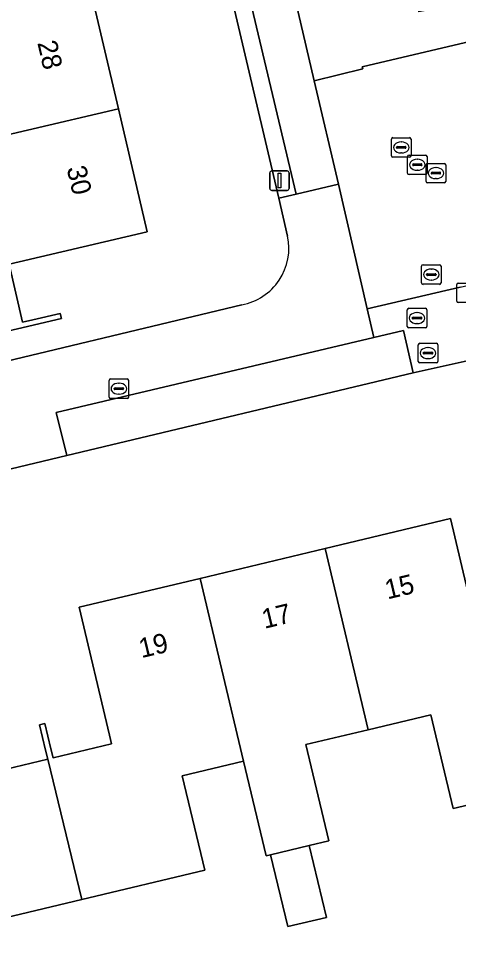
# Model space of a CAD drawing. Extents: x 157648 to 158502, y 379212 to 380938.
# Drawn here: x 158099.34 to 158121.86, y 380779.75 to 380827.8 of the extents above; entities that cross this region are included whole.
import ezdxf

# ---------------------------------------------------------------- set-up
doc = ezdxf.new("R2010")
doc.units = 0
for name, color, linetype in [('IMGEO_Brandkraan', 7, 'Continuous'), ('IMGEO_Erf', 7, 'Continuous'), ('IMGEO_Kolk', 7, 'Continuous'), ('IMGEO_Lichtmast', 7, 'Continuous'), ('IMGEO_Pand', 7, 'Continuous'), ('IMGEO_Pand_nummerreeks', 7, 'Continuous'), ('IMGEO_Parkeervlak_open', 7, 'Continuous'), ('IMGEO_Rijbaan_lokaal_open', 7, 'Continuous'), ('IMGEO_Rioolput', 7, 'Continuous'), ('IMGEO_Voetpad_open', 7, 'Continuous')]:
    doc.layers.add(name, color=color, linetype=linetype)

msp = doc.modelspace()

# ---------------------------------------------------------------- linework, layer by layer
at = {"layer": 'IMGEO_Brandkraan'}
for p, q in [((158119.808, 380810.256), (158119.808, 380811.108)), ((158119.883, 380811.182), (158120.735, 380811.182)), ((158120.296, 380810.962), (158120.321, 380810.962)), ((158120.809, 380811.108), (158120.809, 380810.256)), ((158120.067, 380810.676), (158120.067, 380810.688)), ((158120.505, 380810.639), (158120.107, 380810.639)), ((158120.11, 380810.725), (158120.508, 380810.725)), ((158120.319, 380810.402), (158120.294, 380810.402)), ((158120.551, 380810.688), (158120.551, 380810.676)), ((158120.735, 380810.182), (158119.883, 380810.182))]:
    msp.add_line(p, q, dxfattribs=at)
for points in [[(158119.808, 380810.256), (158119.808, 380811.108)], [(158119.883, 380811.182), (158120.735, 380811.182)], [(158120.809, 380811.108), (158120.809, 380810.256)], [(158120.735, 380810.182), (158119.883, 380810.182)]]:
    msp.add_lwpolyline(points, dxfattribs=at)
for centre, radius, start, end in [((158119.885, 380811.106), 0.0765, 91.552, 178.448), ((158119.885, 380811.106), 0.0765, 91.552, 178.448), ((158120.733, 380811.106), 0.0765, 1.552, 88.448), ((158120.733, 380811.106), 0.0765, 1.552, 88.448), ((158120.107, 380810.685), 0.0403, 85.8775, 175.7526), ((158120.104, 380810.675), 0.0366, 178.938, 274.7102), ((158120.508, 380810.682), 0.043, 264.8664, 352.4533), ((158120.512, 380810.687), 0.0386, 1.7309, 96.639), ((158119.885, 380810.258), 0.0765, 181.552, 268.448), ((158119.885, 380810.258), 0.0765, 181.552, 268.448), ((158120.733, 380810.258), 0.0765, 271.552, 358.448), ((158120.733, 380810.258), 0.0765, 271.552, 358.448)]:
    msp.add_arc(centre, radius, start, end, dxfattribs=at)
for centre, major_axis, ratio, start_param, end_param in [((158120.295, 380810.682), (-0.387, 0.002), 0.722429, 4.712389, 7.853982), ((158120.32, 380810.682), (-0.39, 0.002), 0.717154, 1.570796, 4.712389)]:
    msp.add_ellipse(centre, major_axis=major_axis, ratio=ratio, start_param=start_param, end_param=end_param, dxfattribs=at)
at = {"layer": 'IMGEO_Erf'}
for points in [[(158112.661, 380818.608), (158109.015, 380834.139), (158111.901, 380834.843), (158108.155, 380850.952), (158098.578, 380848.911), (158098.721, 380848.273), (158081.927, 380844.31), (158083.842, 380835.218), (158083.573, 380834.808), (158085.236, 380827.701), (158085.65, 380825.523), (158085.654, 380825.501), (158080.898, 380824.355), (158081.233, 380821.82), (158083.782, 380822.407), (158084.461, 380819.455), (158081.913, 380818.868), (158082.159, 380817.801), (158083.472, 380818.135), (158085.867, 380807.201), (158095.372, 380809.473), (158110.763, 380813.16)], [(158102.923, 380829.722), (158104.45, 380823.191), (158105.923, 380816.888), (158099.37, 380815.357), (158098.844, 380815.234), (158099.539, 380812.265), (158100.065, 380812.388), (158101.466, 380812.716), (158101.528, 380812.45), (158092.502, 380810.34), (158091.032, 380816.63), (158095.864, 380817.759), (158095.105, 380821.005), (158094.347, 380824.251), (158089.612, 380823.144), (158088.882, 380826.268), (158088.37, 380828.461)], [(158113.115, 380816.675), (158112.661, 380818.608)], [(158122.924, 380810.424), (158119.554, 380809.668), (158101.803, 380805.439), (158080.044, 380800.241), (158087.197, 380759.348)], [(158086.779, 380778.918), (158083.38, 380793.171), (158089.674, 380794.672), (158096.153, 380796.217), (158097.717, 380789.661), (158097.832, 380789.177), (158100.83, 380789.892), (158100.72, 380790.357), (158100.413, 380791.653), (158100.684, 380791.718), (158100.992, 380790.419), (158101.102, 380789.956), (158104.099, 380790.671), (158103.993, 380791.115), (158102.43, 380797.671), (158108.628, 380799.149), (158115.035, 380800.677), (158121.466, 380802.212), (158123.132, 380795.125)], [(158126.111, 380788.429), (158121.596, 380787.367), (158120.451, 380792.165), (158117.248, 380791.401), (158114.043, 380790.637), (158115.219, 380785.708), (158114.224, 380785.471), (158115.101, 380781.794), (158113.123, 380781.322), (158112.246, 380784.999), (158112.016, 380784.944), (158110.859, 380789.796), (158107.719, 380789.047), (158108.871, 380784.219), (158102.572, 380782.717), (158096.276, 380781.216), (158095.657, 380783.815), (158092.447, 380783.05), (158091.912, 380785.292), (158088.703, 380784.527), (158089.865, 380779.654)]]:
    msp.add_lwpolyline(points, dxfattribs=at)
msp.add_arc((158110.248, 380816.049), 2.934, 280.1029, 12.3216, dxfattribs=at)
at = {"layer": 'IMGEO_Kolk'}
for p, q in [((158119.259, 380819.896), (158119.259, 380820.748)), ((158119.334, 380820.822), (158120.186, 380820.822)), ((158119.561, 380820.365), (158119.959, 380820.365)), ((158119.747, 380820.602), (158119.772, 380820.602)), ((158120.26, 380820.748), (158120.26, 380819.896)), ((158119.518, 380820.316), (158119.518, 380820.328)), ((158119.956, 380820.279), (158119.558, 380820.279)), ((158119.77, 380820.042), (158119.745, 380820.042)), ((158120.002, 380820.328), (158120.002, 380820.316)), ((158120.186, 380819.822), (158119.334, 380819.822)), ((158119.244, 380812.048), (158119.244, 380812.9)), ((158119.319, 380812.974), (158120.171, 380812.974)), ((158119.732, 380812.754), (158119.757, 380812.754)), ((158120.245, 380812.9), (158120.245, 380812.048)), ((158119.503, 380812.468), (158119.503, 380812.48)), ((158119.941, 380812.431), (158119.543, 380812.431)), ((158119.546, 380812.517), (158119.944, 380812.517)), ((158119.755, 380812.194), (158119.73, 380812.194)), ((158119.987, 380812.48), (158119.987, 380812.468)), ((158120.171, 380811.974), (158119.319, 380811.974)), ((158104.047, 380809.359), (158104.899, 380809.359)), ((158103.972, 380808.433), (158103.972, 380809.285)), ((158104.231, 380808.853), (158104.231, 380808.865)), ((158104.274, 380808.902), (158104.672, 380808.902)), ((158104.46, 380809.139), (158104.485, 380809.139)), ((158104.715, 380808.865), (158104.715, 380808.853)), ((158104.973, 380809.285), (158104.973, 380808.433)), ((158104.899, 380808.359), (158104.047, 380808.359)), ((158104.669, 380808.816), (158104.271, 380808.816)), ((158104.483, 380808.579), (158104.458, 380808.579))]:
    msp.add_line(p, q, dxfattribs=at)
for points in [[(158119.259, 380819.896), (158119.259, 380820.748)], [(158119.334, 380820.822), (158120.186, 380820.822)], [(158120.26, 380820.748), (158120.26, 380819.896)], [(158120.186, 380819.822), (158119.334, 380819.822)], [(158119.244, 380812.048), (158119.244, 380812.9)], [(158119.319, 380812.974), (158120.171, 380812.974)], [(158120.245, 380812.9), (158120.245, 380812.048)], [(158120.171, 380811.974), (158119.319, 380811.974)], [(158104.047, 380809.359), (158104.899, 380809.359)], [(158103.972, 380808.433), (158103.972, 380809.285)], [(158104.973, 380809.285), (158104.973, 380808.433)], [(158104.899, 380808.359), (158104.047, 380808.359)]]:
    msp.add_lwpolyline(points, dxfattribs=at)
for centre, radius, start, end in [((158119.336, 380820.746), 0.0765, 91.552, 178.448), ((158119.336, 380820.746), 0.0765, 91.552, 178.448), ((158119.558, 380820.325), 0.0403, 85.8775, 175.7526), ((158119.963, 380820.327), 0.0386, 1.7309, 96.639), ((158120.184, 380820.746), 0.0765, 1.552, 88.448), ((158120.184, 380820.746), 0.0765, 1.552, 88.448), ((158119.336, 380819.898), 0.0765, 181.552, 268.448), ((158119.336, 380819.898), 0.0765, 181.552, 268.448), ((158119.555, 380820.315), 0.0366, 178.938, 274.7102), ((158119.959, 380820.322), 0.043, 264.8664, 352.4533), ((158120.184, 380819.898), 0.0765, 271.552, 358.448), ((158120.184, 380819.898), 0.0765, 271.552, 358.448), ((158119.321, 380812.898), 0.0765, 91.552, 178.448), ((158119.321, 380812.898), 0.0765, 91.552, 178.448), ((158120.169, 380812.898), 0.0765, 1.552, 88.448), ((158120.169, 380812.898), 0.0765, 1.552, 88.448), ((158119.543, 380812.477), 0.0403, 85.8775, 175.7526), ((158119.54, 380812.467), 0.0366, 178.938, 274.7102), ((158119.944, 380812.474), 0.043, 264.8664, 352.4533), ((158119.948, 380812.479), 0.0386, 1.7309, 96.639), ((158119.321, 380812.05), 0.0765, 181.552, 268.448), ((158119.321, 380812.05), 0.0765, 181.552, 268.448), ((158120.169, 380812.05), 0.0765, 271.552, 358.448), ((158120.169, 380812.05), 0.0765, 271.552, 358.448), ((158104.049, 380809.283), 0.0765, 91.552, 178.448), ((158104.049, 380809.283), 0.0765, 91.552, 178.448), ((158104.897, 380809.283), 0.0765, 1.552, 88.448), ((158104.897, 380809.283), 0.0765, 1.552, 88.448), ((158104.271, 380808.862), 0.0403, 85.8775, 175.7526), ((158104.268, 380808.852), 0.0366, 178.938, 274.7102), ((158104.672, 380808.859), 0.043, 264.8664, 352.4533), ((158104.676, 380808.864), 0.0386, 1.7309, 96.639), ((158104.049, 380808.435), 0.0765, 181.552, 268.448), ((158104.049, 380808.435), 0.0765, 181.552, 268.448), ((158104.897, 380808.435), 0.0765, 271.552, 358.448), ((158104.897, 380808.435), 0.0765, 271.552, 358.448)]:
    msp.add_arc(centre, radius, start, end, dxfattribs=at)
for centre, major_axis, ratio, start_param, end_param in [((158119.746, 380820.322), (-0.387, 0.002), 0.722429, 4.712389, 7.853982), ((158119.771, 380820.322), (-0.39, 0.002), 0.717154, 1.570796, 4.712389), ((158119.731, 380812.474), (-0.387, 0.002), 0.722429, 4.712389, 7.853982), ((158119.756, 380812.474), (-0.39, 0.002), 0.717154, 1.570796, 4.712389), ((158104.459, 380808.859), (-0.387, 0.002), 0.722429, 4.712389, 7.853982), ((158104.484, 380808.859), (-0.39, 0.002), 0.717154, 1.570796, 4.712389)]:
    msp.add_ellipse(centre, major_axis=major_axis, ratio=ratio, start_param=start_param, end_param=end_param, dxfattribs=at)
at = {"layer": 'IMGEO_Lichtmast'}
for p, q in [((158112.204, 380819.111), (158112.204, 380819.911)), ((158112.204, 380819.911), (158112.204, 380819.111)), ((158112.304, 380820.011), (158113.094, 380820.011)), ((158113.094, 380820.011), (158112.304, 380820.011)), ((158113.194, 380819.911), (158113.194, 380819.111)), ((158113.194, 380819.111), (158113.194, 380819.911)), ((158113.094, 380819.011), (158112.304, 380819.011)), ((158112.304, 380819.011), (158113.094, 380819.011))]:
    msp.add_line(p, q, dxfattribs=at)
msp.add_lwpolyline([(158112.624, 380819.886), (158112.774, 380819.886), (158112.774, 380819.136), (158112.624, 380819.136), (158112.624, 380819.886)], dxfattribs=at)
for centre, start, end in [((158112.304, 380819.911), 90, 180), ((158112.304, 380819.911), 90, 180), ((158113.094, 380819.911), 0, 90), ((158113.094, 380819.911), 360, 90), ((158112.304, 380819.111), 180, 270), ((158112.304, 380819.111), 180, 270), ((158113.094, 380819.111), 270, 0), ((158113.094, 380819.111), 270, 0)]:
    msp.add_arc(centre, 0.1, start, end, dxfattribs=at)
at = {"layer": 'IMGEO_Pand'}
for points in [[(158100.707, 380829.204), (158093.575, 380827.456), (158088.882, 380826.268), (158089.612, 380823.144), (158094.347, 380824.251), (158095.105, 380821.005), (158104.45, 380823.191), (158102.923, 380829.722), (158101.196, 380829.318)], [(158095.105, 380821.005), (158095.864, 380817.759), (158091.032, 380816.63), (158092.502, 380810.34), (158101.528, 380812.45), (158101.466, 380812.716), (158100.065, 380812.388), (158099.539, 380812.265), (158098.844, 380815.234), (158099.37, 380815.357), (158105.923, 380816.888), (158104.45, 380823.191)], [(158115.035, 380800.677), (158117.248, 380791.401), (158120.451, 380792.165), (158121.596, 380787.367), (158126.111, 380788.429), (158128.019, 380788.878), (158125.933, 380797.747), (158125.658, 380797.682), (158126.093, 380795.831), (158123.132, 380795.125), (158121.466, 380802.212)], [(158115.035, 380800.677), (158108.628, 380799.149), (158110.859, 380789.796), (158112.016, 380784.944), (158112.246, 380784.999), (158114.224, 380785.471), (158115.219, 380785.708), (158114.043, 380790.637), (158117.248, 380791.401)], [(158100.83, 380789.892), (158102.572, 380782.717), (158108.871, 380784.219), (158107.719, 380789.047), (158110.859, 380789.796), (158108.628, 380799.149), (158102.43, 380797.671), (158103.993, 380791.115), (158104.099, 380790.671), (158101.102, 380789.956), (158100.992, 380790.419), (158100.684, 380791.718), (158100.413, 380791.653), (158100.72, 380790.357)], [(158100.83, 380789.892), (158097.832, 380789.177), (158097.717, 380789.661), (158096.153, 380796.217), (158089.674, 380794.672), (158091.912, 380785.292), (158092.447, 380783.05), (158095.657, 380783.815), (158096.276, 380781.216), (158102.572, 380782.717)], [(158114.224, 380785.471), (158112.246, 380784.999), (158113.123, 380781.322), (158115.101, 380781.794)]]:
    msp.add_lwpolyline(points, close=True, dxfattribs=at)
at = {"layer": 'IMGEO_Parkeervlak_open'}
for points in [[(158114.479, 380824.622), (158113.239, 380829.916), (158111.04, 380829.398), (158113.552, 380818.819), (158115.724, 380819.327)], [(158119.554, 380809.668), (158119.044, 380811.842), (158117.53, 380811.484), (158101.267, 380807.637), (158101.803, 380805.439)]]:
    msp.add_lwpolyline(points, close=True, dxfattribs=at)
at = {"layer": 'IMGEO_Rijbaan_lokaal_open'}
msp.add_lwpolyline([(158127.817, 380827.893), (158116.939, 380825.329), (158116.965, 380825.228), (158114.479, 380824.622), (158115.724, 380819.327), (158117.193, 380812.948), (158121.954, 380814.064), (158124.652, 380814.696), (158124.54, 380815.172), (158126.195, 380819.238), (158128.598, 380819.803), (158132.721, 380820.756), (158133.896, 380821.025), (158133.871, 380821.126), (158134.261, 380821.217), (158153.272, 380825.665)], dxfattribs=at)
at = {"layer": 'IMGEO_Rioolput'}
for p, q in [((158118.436, 380820.784), (158118.436, 380821.636)), ((158118.511, 380821.71), (158119.363, 380821.71)), ((158118.924, 380821.49), (158118.949, 380821.49)), ((158119.437, 380821.636), (158119.437, 380820.784)), ((158118.695, 380821.204), (158118.695, 380821.216)), ((158119.133, 380821.167), (158118.735, 380821.167)), ((158118.738, 380821.253), (158119.136, 380821.253)), ((158118.947, 380820.93), (158118.922, 380820.93)), ((158119.179, 380821.216), (158119.179, 380821.204)), ((158119.363, 380820.71), (158118.511, 380820.71)), ((158120.287, 380820.395), (158121.139, 380820.395)), ((158120.212, 380819.469), (158120.212, 380820.321)), ((158120.471, 380819.889), (158120.471, 380819.901)), ((158120.514, 380819.938), (158120.912, 380819.938)), ((158120.7, 380820.175), (158120.725, 380820.175)), ((158120.955, 380819.901), (158120.955, 380819.889)), ((158121.213, 380820.321), (158121.213, 380819.469)), ((158120.909, 380819.852), (158120.511, 380819.852)), ((158120.723, 380819.615), (158120.698, 380819.615)), ((158121.139, 380819.395), (158120.287, 380819.395)), ((158119.976, 380814.276), (158119.976, 380815.128)), ((158120.051, 380815.202), (158120.903, 380815.202)), ((158120.977, 380815.128), (158120.977, 380814.276)), ((158120.235, 380814.696), (158120.235, 380814.708)), ((158120.673, 380814.659), (158120.275, 380814.659)), ((158120.278, 380814.745), (158120.676, 380814.745)), ((158120.464, 380814.982), (158120.489, 380814.982)), ((158120.719, 380814.708), (158120.719, 380814.696)), ((158120.903, 380814.202), (158120.051, 380814.202)), ((158120.487, 380814.422), (158120.462, 380814.422)), ((158121.781, 380813.34), (158121.781, 380814.192)), ((158121.856, 380814.266), (158122.708, 380814.266)), ((158122.708, 380813.266), (158121.856, 380813.266))]:
    msp.add_line(p, q, dxfattribs=at)
for points in [[(158118.436, 380820.784), (158118.436, 380821.636)], [(158118.511, 380821.71), (158119.363, 380821.71)], [(158119.437, 380821.636), (158119.437, 380820.784)], [(158119.363, 380820.71), (158118.511, 380820.71)], [(158120.287, 380820.395), (158121.139, 380820.395)], [(158120.212, 380819.469), (158120.212, 380820.321)], [(158121.213, 380820.321), (158121.213, 380819.469)], [(158121.139, 380819.395), (158120.287, 380819.395)], [(158119.976, 380814.276), (158119.976, 380815.128)], [(158120.051, 380815.202), (158120.903, 380815.202)], [(158120.977, 380815.128), (158120.977, 380814.276)], [(158120.903, 380814.202), (158120.051, 380814.202)], [(158121.781, 380813.34), (158121.781, 380814.192)], [(158121.856, 380814.266), (158122.708, 380814.266)], [(158122.708, 380813.266), (158121.856, 380813.266)]]:
    msp.add_lwpolyline(points, dxfattribs=at)
for centre, radius, start, end in [((158118.513, 380821.634), 0.0765, 91.552, 178.448), ((158118.513, 380821.634), 0.0765, 91.552, 178.448), ((158119.361, 380821.634), 0.0765, 1.552, 88.448), ((158119.361, 380821.634), 0.0765, 1.552, 88.448), ((158118.735, 380821.213), 0.0403, 85.8775, 175.7526), ((158118.732, 380821.203), 0.0366, 178.938, 274.7102), ((158119.136, 380821.21), 0.043, 264.8664, 352.4533), ((158119.14, 380821.215), 0.0386, 1.7309, 96.639), ((158118.513, 380820.786), 0.0765, 181.552, 268.448), ((158118.513, 380820.786), 0.0765, 181.552, 268.448), ((158119.361, 380820.786), 0.0765, 271.552, 358.448), ((158119.361, 380820.786), 0.0765, 271.552, 358.448), ((158120.289, 380820.319), 0.0765, 91.552, 178.448), ((158120.289, 380820.319), 0.0765, 91.552, 178.448), ((158121.137, 380820.319), 0.0765, 1.552, 88.448), ((158121.137, 380820.319), 0.0765, 1.552, 88.448), ((158120.511, 380819.898), 0.0403, 85.8775, 175.7526), ((158120.508, 380819.888), 0.0366, 178.938, 274.7102), ((158120.912, 380819.895), 0.043, 264.8664, 352.4533), ((158120.916, 380819.9), 0.0386, 1.7309, 96.639), ((158120.289, 380819.471), 0.0765, 181.552, 268.448), ((158120.289, 380819.471), 0.0765, 181.552, 268.448), ((158121.137, 380819.471), 0.0765, 271.552, 358.448), ((158121.137, 380819.471), 0.0765, 271.552, 358.448), ((158120.053, 380815.126), 0.0765, 91.552, 178.448), ((158120.053, 380815.126), 0.0765, 91.552, 178.448), ((158120.901, 380815.126), 0.0765, 1.552, 88.448), ((158120.901, 380815.126), 0.0765, 1.552, 88.448), ((158120.275, 380814.705), 0.0403, 85.8775, 175.7526), ((158120.272, 380814.695), 0.0366, 178.938, 274.7102), ((158120.676, 380814.702), 0.043, 264.8664, 352.4533), ((158120.68, 380814.707), 0.0386, 1.7309, 96.639), ((158120.053, 380814.278), 0.0765, 181.552, 268.448), ((158120.053, 380814.278), 0.0765, 181.552, 268.448), ((158120.901, 380814.278), 0.0765, 271.552, 358.448), ((158120.901, 380814.278), 0.0765, 271.552, 358.448), ((158121.858, 380814.19), 0.0765, 91.552, 178.448), ((158121.858, 380814.19), 0.0765, 91.552, 178.448), ((158121.858, 380813.342), 0.0765, 181.552, 268.448), ((158121.858, 380813.342), 0.0765, 181.552, 268.448)]:
    msp.add_arc(centre, radius, start, end, dxfattribs=at)
for centre, major_axis, ratio, start_param, end_param in [((158118.923, 380821.21), (-0.387, 0.002), 0.722429, 4.712389, 7.853982), ((158118.948, 380821.21), (-0.39, 0.002), 0.717154, 1.570796, 4.712389), ((158120.699, 380819.895), (-0.387, 0.002), 0.722429, 4.712389, 7.853982), ((158120.724, 380819.895), (-0.39, 0.002), 0.717154, 1.570796, 4.712389), ((158120.463, 380814.702), (-0.387, 0.002), 0.722429, 4.712389, 7.853982), ((158120.488, 380814.702), (-0.39, 0.002), 0.717154, 1.570796, 4.712389)]:
    msp.add_ellipse(centre, major_axis=major_axis, ratio=ratio, start_param=start_param, end_param=end_param, dxfattribs=at)
at = {"layer": 'IMGEO_Voetpad_open'}
msp.add_lwpolyline([(158127.817, 380827.893), (158127.381, 380829.845), (158127.204, 380829.803), (158121.806, 380828.52), (158119.836, 380828.149), (158117.095, 380839.543), (158119.322, 380842.743), (158119.428, 380842.771), (158117.831, 380849.402), (158114.854, 380848.695), (158111.876, 380847.987), (158110.419, 380854.164), (158109.447, 380853.986), (158107.551, 380853.548), (158108.155, 380850.952), (158111.901, 380834.843), (158109.015, 380834.139), (158112.661, 380818.608), (158113.552, 380818.819), (158111.04, 380829.398), (158113.239, 380829.916), (158114.479, 380824.622), (158116.965, 380825.228), (158116.939, 380825.329)], close=True, dxfattribs=at)
for points in [[(158101.267, 380807.637), (158117.53, 380811.484), (158117.193, 380812.948), (158115.724, 380819.327), (158113.552, 380818.819), (158112.661, 380818.608), (158113.115, 380816.675)], [(158121.954, 380814.064), (158117.193, 380812.948), (158117.53, 380811.484), (158119.044, 380811.842), (158119.554, 380809.668), (158122.924, 380810.424)], [(158110.763, 380813.16), (158095.372, 380809.473), (158085.867, 380807.201), (158084.907, 380806.971), (158085.136, 380805.991), (158079.204, 380804.706), (158080.044, 380800.241), (158101.803, 380805.439), (158101.267, 380807.637)]]:
    msp.add_lwpolyline(points, dxfattribs=at)
msp.add_arc((158110.248, 380816.049), 2.934, 280.1029, 12.3216, dxfattribs=at)

# ---------------------------------------------------------------- texts
at = {"layer": 'IMGEO_Pand_nummerreeks'}
for s, rotation, p in [('28', 283.1569, (158100.291, 380826.569)), ('30', 283.1569, (158101.791, 380820.152)), ('15', 13.4171, (158118.231, 380798.068)), ('17', 13.4187, (158111.928, 380796.564)), ('19', 13.4171, (158105.627, 380795.062))]:
    msp.add_text(s, height=1, rotation=rotation, dxfattribs=at).set_placement(p)

doc.saveas('drawing.dxf')
